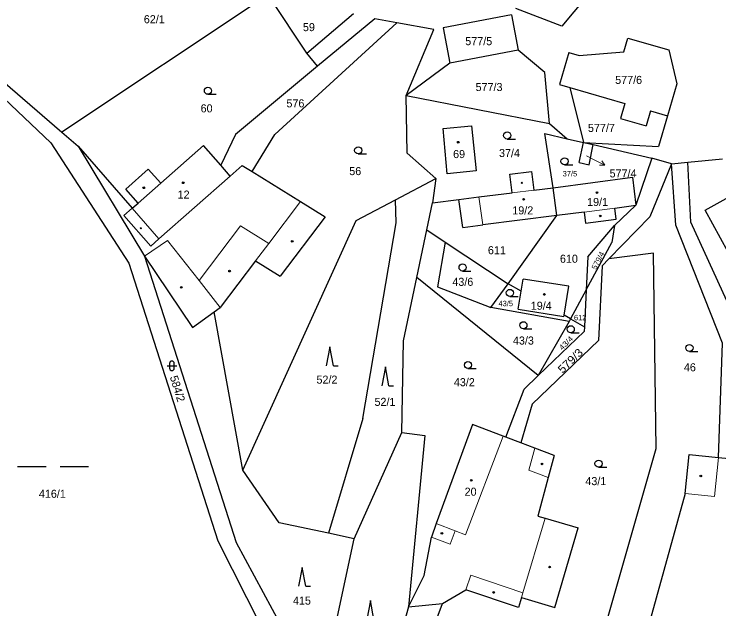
# Model space of a CAD drawing. Extents: x -664548 to -662415, y -1069720 to -1068208.
# Drawn here: x -663758.5 to -663609.5, y -1069095.9 to -1068970.2 of the extents above; entities that cross this region are included whole.
import ezdxf
from ezdxf.enums import TextEntityAlignment as Align

# ---------------------------------------------------------------- set-up
doc = ezdxf.new("R2010")
doc.units = 0
doc.header["$LTSCALE"] = 0.68
for name, color, linetype, lineweight in [('1', 7, 'Continuous', 25), ('3', 7, 'Continuous', 25), ('4', 7, 'Continuous', 13), ('5', 7, 'Continuous', 25), ('7', 7, 'Continuous', 13)]:
    doc.layers.add(name, color=color, linetype=linetype, lineweight=lineweight)
doc.layers.add('2', color=7, linetype='Continuous')

msp = doc.modelspace()

# ---------------------------------------------------------------- linework, layer by layer
at = {"layer": '1'}
for p, q in [((-663704.81, -1068966.13), (-663748.36, -1068995.22)), ((-663696.63, -1068978.49), (-663704.81, -1068966.13)), ((-663637.34, -1068966.28), (-663642.72, -1068972.79)), ((-663642.72, -1068972.79), (-663652.45, -1068969.05)), ((-663696.63, -1068978.49), (-663686.76, -1068970.1)), ((-663653.37, -1068970.36), (-663667.81, -1068973.12)), ((-663653.37, -1068970.36), (-663651.94, -1068977.83)), ((-663703.4, -1068995.71), (-663677.56, -1068972.07)), ((-663682.23, -1068971.21), (-663694.33, -1068981.27)), ((-663677.56, -1068972.07), (-663682.23, -1068971.21)), ((-663669.77, -1068973.49), (-663677.56, -1068972.07)), ((-663675.59, -1068987.41), (-663669.77, -1068973.49)), ((-663667.81, -1068973.12), (-663666.38, -1068980.59)), ((-663629.64, -1068978.19), (-663628.8, -1068975.3)), ((-663628.8, -1068975.3), (-663620.15, -1068977.8)), ((-663694.33, -1068981.27), (-663696.63, -1068978.49)), ((-663651.94, -1068977.83), (-663666.38, -1068980.59)), ((-663646.34, -1068982.56), (-663651.94, -1068977.83)), ((-663641.27, -1068978.37), (-663643.22, -1068985.12)), ((-663641.27, -1068978.37), (-663639.06, -1068979.01)), ((-663639.06, -1068979.01), (-663629.64, -1068978.19)), ((-663620.15, -1068977.8), (-663618.44, -1068984.97)), ((-663694.33, -1068981.27), (-663711.67, -1068995.69)), ((-663666.38, -1068980.59), (-663675.59, -1068987.41)), ((-663762.53, -1068983.07), (-663748.36, -1068995.22)), ((-663645.31, -1068993.33), (-663646.34, -1068982.56)), ((-663643.22, -1068985.12), (-663641.01, -1068985.76)), ((-663641.01, -1068985.76), (-663638.13, -1068997.34)), ((-663641.01, -1068985.76), (-663629.39, -1068989.12)), ((-663618.44, -1068984.97), (-663620.39, -1068991.72)), ((-663762.6, -1068986.14), (-663750.68, -1068997.45)), ((-663675.38, -1068999.61), (-663675.59, -1068987.41)), ((-663675.59, -1068987.41), (-663645.31, -1068993.33)), ((-663629.39, -1068989.12), (-663630.3, -1068992.29)), ((-663624.01, -1068990.68), (-663624.92, -1068993.85)), ((-663624.01, -1068990.68), (-663620.39, -1068991.72)), ((-663620.39, -1068991.72), (-663622.27, -1068998.23)), ((-663645.31, -1068993.33), (-663641.63, -1068996.58)), ((-663630.3, -1068992.29), (-663624.92, -1068993.85)), ((-663666.95, -1069004), (-663667.82, -1068994.38)), ((-663748.36, -1068995.22), (-663744.93, -1068998.17)), ((-663711.67, -1068995.69), (-663714.77, -1069002.19)), ((-663708.17, -1069003.5), (-663703.4, -1068995.71)), ((-663646.32, -1068995.46), (-663641.63, -1068996.58)), ((-663644.56, -1069006.94), (-663646.32, -1068995.46)), ((-663750.68, -1068997.45), (-663734.19, -1069022.84)), ((-663641.63, -1068996.58), (-663638.13, -1068997.34)), ((-663639.1, -1069001.6), (-663638.13, -1068997.34)), ((-663638.13, -1068997.34), (-663636.11, -1068997.8)), ((-663638.13, -1068997.34), (-663622.27, -1068998.23)), ((-663636.97, -1069002.09), (-663636.11, -1068997.8)), ((-663636.11, -1068997.8), (-663623.68, -1069000.66)), ((-663744.93, -1068998.17), (-663733.5, -1069011.28)), ((-663744.93, -1068998.17), (-663730.94, -1069021.38)), ((-663727.48, -1069005.97), (-663718.45, -1068998.01)), ((-663714.77, -1069002.19), (-663718.45, -1068998.01)), ((-663669.34, -1069004.98), (-663675.38, -1068999.61)), ((-663623.68, -1069000.66), (-663627.07, -1069010.6)), ((-663619.58, -1069001.91), (-663623.68, -1069000.66)), ((-663616.1, -1069001.55), (-663608.81, -1069000.81)), ((-663712.78, -1069004.45), (-663714.77, -1069002.19)), ((-663710.25, -1069002.21), (-663712.78, -1069004.45)), ((-663710.25, -1069002.21), (-663708.17, -1069003.5)), ((-663639.1, -1069001.6), (-663636.97, -1069002.09)), ((-663619.58, -1069001.91), (-663624.11, -1069013.09)), ((-663619.58, -1069001.91), (-663616.1, -1069001.55)), ((-663618.63, -1069014.85), (-663619.58, -1069001.91)), ((-663615.5, -1069014.24), (-663616.1, -1069001.55)), ((-663734.86, -1069007.2), (-663730.11, -1069003)), ((-663727.48, -1069005.97), (-663730.11, -1069003)), ((-663708.17, -1069003.5), (-663697.94, -1069009.85)), ((-663660.85, -1069003.38), (-663666.95, -1069004)), ((-663653.71, -1069004.03), (-663649.14, -1069003.47)), ((-663649.14, -1069003.47), (-663648.66, -1069007.44)), ((-663677.86, -1069009.48), (-663669.34, -1069004.98)), ((-663669.34, -1069004.98), (-663670.07, -1069010.15)), ((-663653.23, -1069008), (-663653.71, -1069004.03)), ((-663644.56, -1069006.94), (-663627.83, -1069004.68)), ((-663627.83, -1069004.68), (-663627.07, -1069010.6)), ((-663732.24, -1069010.17), (-663734.86, -1069007.2)), ((-663660.25, -1069008.86), (-663653.23, -1069008)), ((-663648.66, -1069007.44), (-663644.56, -1069006.94)), ((-663643.76, -1069012.8), (-663644.56, -1069006.94)), ((-663697.94, -1069009.85), (-663692.74, -1069013.08)), ((-663686.21, -1069013.88), (-663677.86, -1069009.48)), ((-663677.76, -1069014.34), (-663677.86, -1069009.48)), ((-663670.07, -1069010.15), (-663664.46, -1069009.41)), ((-663664.46, -1069009.41), (-663660.25, -1069008.86)), ((-663663.64, -1069015.31), (-663664.46, -1069009.41)), ((-663612.47, -1069011.65), (-663607.39, -1069008.88)), ((-663733.5, -1069011.28), (-663732.24, -1069010.17)), ((-663671.27, -1069015.83), (-663670.07, -1069010.15)), ((-663631.22, -1069013.55), (-663631.53, -1069011.22)), ((-663643.76, -1069012.8), (-663659.43, -1069014.78)), ((-663654.09, -1069027.21), (-663643.76, -1069012.8)), ((-663638.02, -1069012.11), (-663643.76, -1069012.8)), ((-663638.02, -1069012.11), (-663637.71, -1069014.4)), ((-663597.91, -1069038.36), (-663612.47, -1069011.65)), ((-663710.12, -1069066.63), (-663686.21, -1069013.88)), ((-663692.74, -1069013.08), (-663702.22, -1069025.61)), ((-663684.81, -1069055.73), (-663677.76, -1069014.34)), ((-663637.71, -1069014.4), (-663631.22, -1069013.55)), ((-663624.11, -1069013.09), (-663632.78, -1069021.98)), ((-663599.17, -1069049.94), (-663615.5, -1069014.24)), ((-663673.39, -1069025.88), (-663671.27, -1069015.83)), ((-663663.64, -1069015.31), (-663659.43, -1069014.78)), ((-663637.23, -1069021.5), (-663631.61, -1069014.9)), ((-663631.61, -1069014.9), (-663632.17, -1069018.5)), ((-663608.76, -1069039.8), (-663618.63, -1069014.85)), ((-663667.39, -1069018.4), (-663654.09, -1069027.21)), ((-663637.58, -1069028.52), (-663632.17, -1069018.5)), ((-663730.94, -1069021.38), (-663720.78, -1069036.48)), ((-663730.94, -1069021.38), (-663711.53, -1069081.92)), ((-663637.23, -1069021.5), (-663637.58, -1069028.52)), ((-663623.38, -1069020.78), (-663632.78, -1069021.98)), ((-663622.82, -1069062.07), (-663623.38, -1069020.78)), ((-663734.19, -1069022.84), (-663715.38, -1069081.53)), ((-663707.43, -1069022.38), (-663714.91, -1069032.27)), ((-663707.43, -1069022.38), (-663702.22, -1069025.61)), ((-663632.78, -1069021.98), (-663634.2, -1069023.44)), ((-663634.2, -1069023.44), (-663634.99, -1069039.19)), ((-663676.21, -1069039.27), (-663673.39, -1069025.88)), ((-663647.72, -1069046.61), (-663673.39, -1069025.88)), ((-663651.33, -1069028.77), (-663650.92, -1069026.24)), ((-663641.28, -1069027.76), (-663650.92, -1069026.24)), ((-663657.72, -1069032.22), (-663654.09, -1069027.21)), ((-663651.33, -1069028.77), (-663654.09, -1069027.21)), ((-663642.26, -1069033.89), (-663641.28, -1069027.76)), ((-663668.98, -1069027.89), (-663657.72, -1069032.22)), ((-663651.94, -1069032.59), (-663651.33, -1069028.77)), ((-663637.58, -1069028.52), (-663640.87, -1069034.67)), ((-663637.58, -1069028.52), (-663637.97, -1069036.31)), ((-663641.21, -1069035.19), (-663657.72, -1069032.22)), ((-663720.78, -1069036.48), (-663716.18, -1069033.18)), ((-663716.18, -1069033.18), (-663714.91, -1069032.27)), ((-663710.12, -1069066.63), (-663716.18, -1069033.18)), ((-663651.94, -1069032.59), (-663642.3, -1069034.13)), ((-663641.21, -1069035.19), (-663647.72, -1069046.61)), ((-663642.3, -1069034.13), (-663642.26, -1069033.89)), ((-663640.87, -1069034.67), (-663642.26, -1069033.89)), ((-663640.87, -1069034.67), (-663641.21, -1069035.19)), ((-663640.87, -1069034.67), (-663637.97, -1069036.31)), ((-663637.97, -1069036.31), (-663638.02, -1069037.3)), ((-663638.02, -1069037.3), (-663647.72, -1069046.61)), ((-663676.57, -1069058.64), (-663676.21, -1069039.27)), ((-663634.99, -1069039.19), (-663649.01, -1069052.64)), ((-663609.65, -1069063.94), (-663608.76, -1069039.8)), ((-663647.72, -1069046.61), (-663650.71, -1069049.48)), ((-663654.58, -1069059.64), (-663650.71, -1069049.48)), ((-663649.01, -1069052.64), (-663651.42, -1069060.85)), ((-663684.81, -1069055.73), (-663692.06, -1069079.95)), ((-663661.63, -1069056.96), (-663669.26, -1069077.91)), ((-663655.14, -1069059.43), (-663661.63, -1069056.96)), ((-663686.64, -1069081.11), (-663676.57, -1069058.64)), ((-663676.57, -1069058.64), (-663671.65, -1069059.26)), ((-663671.65, -1069059.26), (-663675.12, -1069095.52)), ((-663654.58, -1069059.64), (-663655.14, -1069059.43)), ((-663651.42, -1069060.85), (-663654.58, -1069059.64)), ((-663648.45, -1069061.98), (-663651.42, -1069060.85)), ((-663644.36, -1069063.53), (-663648.45, -1069061.98)), ((-663638.3, -1069116.25), (-663622.82, -1069062.07)), ((-663616.65, -1069071.57), (-663615.84, -1069063.33)), ((-663615.84, -1069063.33), (-663609.65, -1069063.94)), ((-663644.36, -1069063.53), (-663645.61, -1069068.15)), ((-663609.65, -1069063.94), (-663604.24, -1069064.47)), ((-663702.43, -1069077.72), (-663710.12, -1069066.63)), ((-663645.61, -1069068.15), (-663647.81, -1069076.31)), ((-663616.65, -1069071.57), (-663625.2, -1069102.36)), ((-663647.81, -1069076.31), (-663646.28, -1069076.76)), ((-663646.28, -1069076.76), (-663639.29, -1069078.82)), ((-663692.06, -1069079.95), (-663702.43, -1069077.72)), ((-663669.26, -1069077.91), (-663670.3, -1069080.75)), ((-663644.24, -1069095.62), (-663639.29, -1069078.82)), ((-663694.06, -1069115.97), (-663686.64, -1069081.11)), ((-663686.64, -1069081.11), (-663692.06, -1069079.95)), ((-663671.81, -1069088.88), (-663670.3, -1069080.75)), ((-663715.38, -1069081.53), (-663704.24, -1069103.68)), ((-663711.53, -1069081.92), (-663700.58, -1069102.12)), ((-663675.12, -1069095.52), (-663671.81, -1069088.88)), ((-663667.95, -1069094.79), (-663663.01, -1069091.88)), ((-663651.86, -1069095.67), (-663663.01, -1069091.88)), ((-663651.23, -1069093.56), (-663651.86, -1069095.67)), ((-663651.23, -1069093.56), (-663644.24, -1069095.62)), ((-663675.12, -1069095.52), (-663683.05, -1069122.67)), ((-663678.33, -1069122.82), (-663667.95, -1069094.79)), ((-663675.12, -1069095.52), (-663667.95, -1069094.79))]:
    msp.add_line(p, q, dxfattribs=at)
for points in [[(-663667.82, -1068994.38), (-663661.83, -1068993.82), (-663660.85, -1069003.38)], [(-663631.53, -1069011.22), (-663627.07, -1069010.6), (-663631.61, -1069014.9)], [(-663671.27, -1069015.83), (-663667.39, -1069018.4), (-663668.98, -1069027.89)]]:
    msp.add_lwpolyline(points, dxfattribs=at)
at = {"layer": '3'}
for p, q in [((-663717.513, -1068987.18), (-663715.763, -1068987.18)), ((-663654.273, -1068996.63), (-663652.523, -1068996.63)), ((-663685.753, -1068999.78), (-663684.003, -1068999.78)), ((-663642.163, -1069002.09), (-663640.413, -1069002.09)), ((-663663.703, -1069024.53), (-663661.953, -1069024.53)), ((-663653.713, -1069029.91), (-663651.963, -1069029.91)), ((-663650.843, -1069036.74), (-663649.093, -1069036.74)), ((-663640.843, -1069037.59), (-663639.093, -1069037.59)), ((-663615.763, -1069041.54), (-663614.013, -1069041.54)), ((-663725.611, -1069044.071), (-663725.611, -1069045.072)), ((-663724.609, -1069045.072), (-663724.609, -1069044.071)), ((-663726.111, -1069044.571), (-663724.109, -1069044.571)), ((-663691, -1069044.57), (-663690.004, -1069044.57)), ((-663662.563, -1069045.15), (-663660.813, -1069045.15)), ((-663679.26, -1069048.79), (-663678.264, -1069048.79)), ((-663757.709, -1069065.84), (-663751.709, -1069065.84)), ((-663748.709, -1069065.84), (-663742.709, -1069065.84)), ((-663634.973, -1069065.99), (-663633.223, -1069065.99)), ((-663696.84, -1069091.16), (-663695.844, -1069091.16))]:
    msp.add_line(p, q, dxfattribs=at)
for points in [[(-663691, -1069044.57), (-663691.75, -1069040.57), (-663692.5, -1069044.57)], [(-663679.26, -1069048.79), (-663680.01, -1069044.79), (-663680.76, -1069048.79)], [(-663696.84, -1069091.16), (-663697.59, -1069087.16), (-663698.34, -1069091.16)], [(-663682.43, -1069098.15), (-663683.18, -1069094.15), (-663683.93, -1069098.15)]]:
    msp.add_lwpolyline(points, dxfattribs=at)
for centre in [(-663717.5129, -1068986.4298), (-663654.2729, -1068995.8798), (-663685.7529, -1068999.0298), (-663642.1629, -1069001.3398), (-663663.7029, -1069023.7798), (-663653.7129, -1069029.1598), (-663650.8429, -1069035.9898), (-663640.8429, -1069036.8398), (-663615.7629, -1069040.7898), (-663662.5629, -1069044.3998), (-663634.9729, -1069065.2398)]:
    msp.add_circle(centre, 0.75, dxfattribs=at)
for centre, start, end in [((-663725.11, -1069044.0709), 0, 180), ((-663725.11, -1069045.0709), 180, 359.98789)]:
    msp.add_arc(centre, 0.5, start, end, dxfattribs=at)
at = {"layer": '4'}
for p, q in [((-663727.85, -1069017.76), (-663712.78, -1069004.45)), ((-663732.24, -1069010.17), (-663727.48, -1069005.97)), ((-663653.23, -1069008), (-663648.66, -1069007.44)), ((-663697.94, -1069009.85), (-663704.66, -1069018.72)), ((-663659.43, -1069014.78), (-663660.25, -1069008.86)), ((-663735.24, -1069012.82), (-663733.5, -1069011.28)), ((-663733.5, -1069011.28), (-663727.85, -1069017.76)), ((-663638.02, -1069012.11), (-663631.53, -1069011.22)), ((-663735.24, -1069012.82), (-663729.59, -1069019.3)), ((-663710.63, -1069015.01), (-663719.38, -1069026.57)), ((-663726.04, -1069018.08), (-663730.94, -1069021.38)), ((-663729.59, -1069019.3), (-663727.85, -1069017.76)), ((-663719.38, -1069026.57), (-663726.04, -1069018.08)), ((-663714.91, -1069032.27), (-663719.38, -1069026.57)), ((-663663.08, -1069080.27), (-663655.14, -1069059.43)), ((-663648.45, -1069061.98), (-663649.7, -1069066.6)), ((-663645.61, -1069068.15), (-663649.7, -1069066.6)), ((-663669.26, -1069077.91), (-663665.26, -1069079.44)), ((-663665.26, -1069079.44), (-663666.34, -1069082.26)), ((-663665.26, -1069079.44), (-663663.08, -1069080.27)), ((-663670.3, -1069080.75), (-663666.34, -1069082.26)), ((-663663.01, -1069091.88), (-663661.97, -1069088.83)), ((-663650.94, -1069092.58), (-663651.23, -1069093.56))]:
    msp.add_line(p, q, dxfattribs=at)
for points in [[(-663710.63, -1069015.01), (-663704.66, -1069018.72), (-663707.43, -1069022.38)], [(-663609.65, -1069063.94), (-663610.46, -1069072.18), (-663616.65, -1069071.57)], [(-663646.28, -1069076.76), (-663650.94, -1069092.58), (-663661.97, -1069088.83)]]:
    msp.add_lwpolyline(points, dxfattribs=at)
at = {"layer": '5'}
for centre, radius in [((-663664.6268, -1068997.3092), 0.175), ((-663731.0668, -1069006.9392), 0.175), ((-663722.7268, -1069005.8792), 0.175), ((-663651.1846, -1069005.8894), 0.1172), ((-663635.2968, -1069007.9392), 0.175), ((-663650.7968, -1069009.3792), 0.175), ((-663634.6068, -1069012.8892), 0.175), ((-663731.6946, -1069015.4894), 0.1172), ((-663699.6968, -1069018.2692), 0.175), ((-663712.9368, -1069024.5492), 0.175), ((-663723.1268, -1069027.9892), 0.175), ((-663646.4168, -1069029.4792), 0.175), ((-663646.9168, -1069065.3092), 0.175), ((-663613.3668, -1069067.8392), 0.175), ((-663661.8668, -1069068.7692), 0.175), ((-663668.0668, -1069079.9792), 0.175), ((-663645.3068, -1069087.0992), 0.175), ((-663657.1168, -1069092.4692), 0.175)]:
    msp.add_circle(centre, radius, dxfattribs=at)
at = {"layer": '7'}
msp.add_line((-663633.636, -1069002.172), (-663634.301, -1069001.272), dxfattribs=at)
msp.add_lwpolyline([(-663637.52, -1069000.18), (-663636.31, -1069000.81), (-663633.636, -1069002.172), (-663634.756, -1069002.164)], dxfattribs=at)

# ---------------------------------------------------------------- texts
at = {"layer": '2'}
for s, height, p in [('62/1', 1.7, (-663731.05, -1068972.165)), ('59', 1.7, (-663697.43, -1068973.834)), ('577/5', 1.7, (-663663.13, -1068976.804)), ('577/6', 1.7, (-663631.46, -1068984.995)), ('577/3', 1.7, (-663660.95, -1068986.495)), ('576', 1.7, (-663700.92, -1068989.945)), ('60', 1.7, (-663719.05, -1068991.005)), ('577/7', 1.7, (-663637.21, -1068995.135)), ('56', 1.7, (-663687.64, -1069004.265)), ('37/5', 1.14, (-663642.55, -1069004.535)), ('577/4', 1.7, (-663632.64, -1069004.745)), ('12', 1.7, (-663723.91, -1069009.225)), ('19/1', 1.7, (-663637.39, -1069010.795)), ('19/2', 1.7, (-663653.19, -1069012.564)), ('611', 1.7, (-663658.35, -1069020.985)), ('610', 1.7, (-663643.13, -1069022.785)), ('43/5', 1.14, (-663656.11, -1069031.964)), ('19/4', 1.7, (-663649.29, -1069032.715)), ('612', 1.14, (-663640.16, -1069034.944)), ('46', 1.7, (-663616.94, -1069045.725)), ('52/2', 1.7, (-663694.57, -1069048.334)), ('43/2', 1.7, (-663665.54, -1069048.875)), ('52/1', 1.7, (-663682.31, -1069053.035)), ('43/1', 1.7, (-663637.76, -1069069.785)), ('416/1', 1.7, (-663753.22, -1069072.465)), ('20', 1.7, (-663663.27, -1069072.025)), ('415', 1.7, (-663699.54, -1069095.045))]:
    msp.add_text(s, height=height, dxfattribs=at).set_placement(p)
for s, p in [('69', (-663664.439, -1069000.665)), ('37/4', (-663653.789, -1069000.445)), ('43/6', (-663663.649, -1069027.665)), ('43/3', (-663650.849, -1069040.074))]:
    msp.add_text(s, height=1.7, dxfattribs=at).set_placement(p, align=Align.CENTER)
for s, height, rotation, width, p in [('579/4', 1.14, 63, 1.05, (-663635.486, -1069024.359)), ('43/4', 1.14, 45, 1.15, (-663642.648, -1069041.381)), ('579/3', 1.7, 44, 1.1, (-663642.594, -1069046.295))]:
    msp.add_text(s, height=height, rotation=rotation, dxfattribs=dict(at, width=width)).set_placement(p)
msp.add_text('584/2', height=1.7, rotation=287, dxfattribs=at).set_placement((-663725.566, -1069046.934))

doc.saveas('drawing.dxf')
